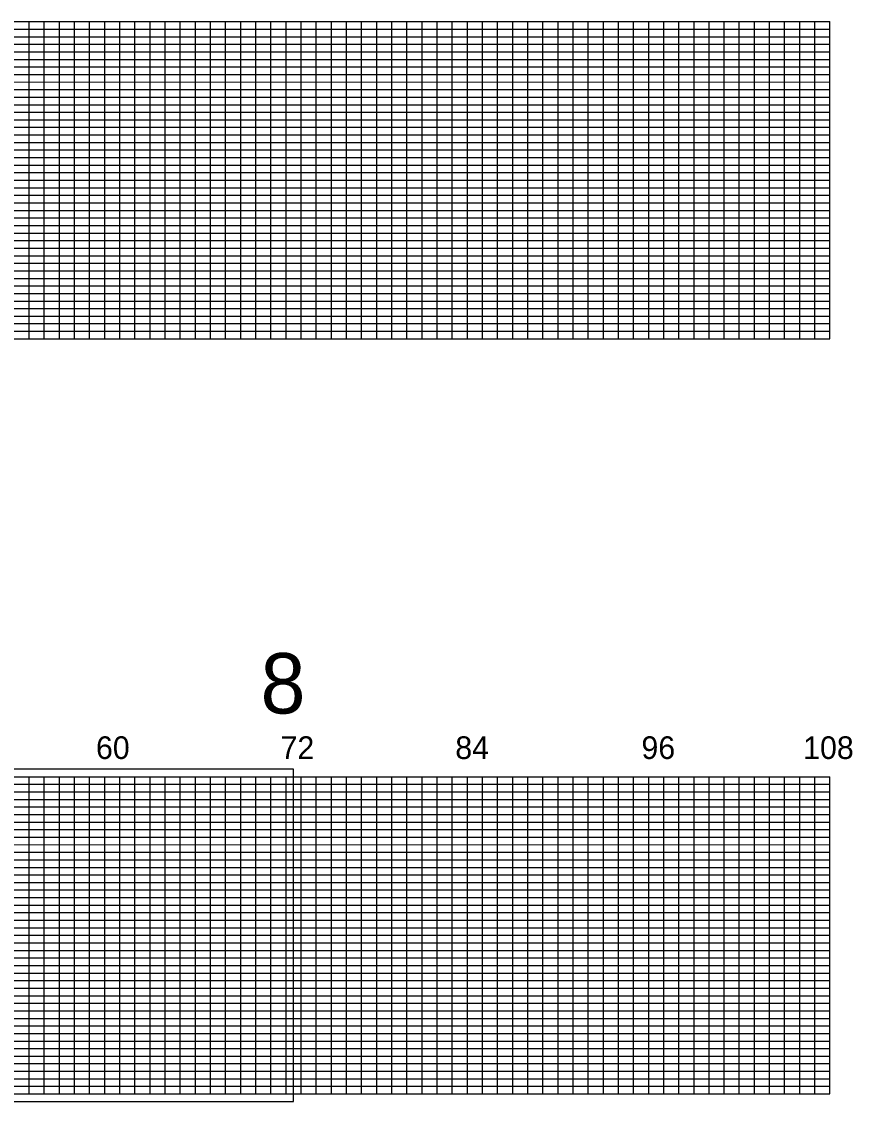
# Model space of a CAD drawing. Extents: x 1950433 to 1956806, y 750939 to 777666.
# Drawn here: x 1954051 to 1956801, y 758439 to 762014 of the extents above; entities that cross this region are included whole.
import ezdxf

# ---------------------------------------------------------------- set-up
doc = ezdxf.new("R2010")
doc.units = 0
for name, color, linetype in [('RD_PD_WallFill', 7, 'Continuous'), ('RD_SHT_IplotShp', 7, 'Continuous'), ('RD_Sketch8', 7, 'Continuous')]:
    doc.layers.add(name, color=color, linetype=linetype)

msp = doc.modelspace()

# ---------------------------------------------------------------- linework, layer by layer
at = {"layer": 'RD_PD_WallFill'}
for p, q in [((1951376.4, 762014.1), (1956726.4, 762014.2)), ((1954076.4, 760964.2), (1954076.4, 762014.2)), ((1954126.4, 760964.2), (1954126.4, 762014.2)), ((1954176.4, 760964.2), (1954176.4, 762014.2)), ((1954226.4, 760964.2), (1954226.4, 762014.2)), ((1954276.4, 760964.2), (1954276.4, 762014.2)), ((1954326.4, 760964.2), (1954326.4, 762014.2)), ((1954376.4, 760964.2), (1954376.4, 762014.2)), ((1954426.4, 760964.2), (1954426.4, 762014.2)), ((1954476.4, 760964.1), (1954476.4, 762014.2)), ((1954526.4, 760964.2), (1954526.4, 762014.2)), ((1954576.4, 760964.2), (1954576.4, 762014.2)), ((1954626.4, 760964.2), (1954626.4, 762014.2)), ((1954676.4, 760964.2), (1954676.4, 762014.2)), ((1954726.4, 760964.2), (1954726.4, 762014.2)), ((1954776.4, 760964.1), (1954776.4, 762014.2)), ((1954826.4, 760964.1), (1954826.4, 762014.2)), ((1954876.4, 760964.2), (1954876.4, 762014.2)), ((1954926.4, 760964.2), (1954926.4, 762014.2)), ((1954976.4, 760964.2), (1954976.4, 762014.2)), ((1955026.4, 760964.2), (1955026.4, 762014.2)), ((1955076.4, 760964.2), (1955076.4, 762014.2)), ((1955126.4, 760964.2), (1955126.4, 762014.2)), ((1955176.4, 760964.2), (1955176.4, 762014.2)), ((1955226.4, 760964.2), (1955226.4, 762014.2)), ((1955276.4, 760964.2), (1955276.4, 762014.2)), ((1955326.4, 760964.2), (1955326.4, 762014.2)), ((1955376.4, 760964.2), (1955376.4, 762014.2)), ((1955426.4, 760964.2), (1955426.4, 762014.2)), ((1955476.4, 760964.2), (1955476.4, 762014.2)), ((1955526.4, 760964.2), (1955526.4, 762014.2)), ((1955576.4, 760964.2), (1955576.4, 762014.2)), ((1955626.4, 760964.2), (1955626.4, 762014.2)), ((1955676.4, 760964.2), (1955676.4, 762014.2)), ((1955726.4, 760964.2), (1955726.4, 762014.2)), ((1955776.4, 760964.2), (1955776.4, 762014.2)), ((1955826.4, 760964.2), (1955826.4, 762014.2)), ((1955876.4, 760964.2), (1955876.4, 762014.2)), ((1955926.4, 760964.2), (1955926.4, 762014.2)), ((1955976.4, 760964.2), (1955976.4, 762014.2)), ((1956026.4, 760964.2), (1956026.4, 762014.2)), ((1956076.4, 760964.2), (1956076.4, 762014.2)), ((1956126.4, 760964.2), (1956126.4, 762014.2)), ((1956176.4, 760964.2), (1956176.4, 762014.2)), ((1956226.4, 760964.2), (1956226.4, 762014.2)), ((1956276.4, 760964.2), (1956276.4, 762014.2)), ((1956326.4, 760964.2), (1956326.4, 762014.2)), ((1956376.4, 760964.2), (1956376.4, 762014.2)), ((1956426.4, 760964.2), (1956426.4, 762014.2)), ((1956476.4, 760964.2), (1956476.4, 762014.2)), ((1956526.4, 760964.2), (1956526.4, 762014.2)), ((1956576.4, 760964.2), (1956576.4, 762014.2)), ((1956626.4, 760964.2), (1956626.4, 762014.2)), ((1956676.4, 760964.2), (1956676.4, 762014.2)), ((1956726.4, 760964.2), (1956726.4, 762014.2)), ((1951826.4, 761989.1), (1956726.4, 761989.1)), ((1951826.4, 761964.1), (1956726.4, 761964.1)), ((1951826.4, 761939.1), (1956726.4, 761939.1)), ((1951826.4, 761914.2), (1956726.4, 761914.1)), ((1951826.4, 761889.1), (1956726.4, 761889.2)), ((1951376.4, 761864.1), (1956726.4, 761864.1)), ((1951376.4, 761839.1), (1956726.4, 761839.1)), ((1951376.4, 761814.1), (1956726.4, 761814.2)), ((1951376.4, 761789.2), (1956726.4, 761789.1)), ((1951376.4, 761764.2), (1956726.4, 761764.2)), ((1951376.4, 761739.1), (1956726.4, 761739.1)), ((1951376.4, 761714.1), (1956726.4, 761714.1)), ((1951376.4, 761689.2), (1956726.4, 761689.1)), ((1951376.4, 761664.1), (1956726.4, 761664.1)), ((1951376.4, 761639.2), (1956726.4, 761639.1)), ((1951376.4, 761614.1), (1956726.4, 761614.1)), ((1951376.4, 761589.1), (1956726.4, 761589.2)), ((1951376.4, 761564.1), (1956726.4, 761564.1)), ((1951376.4, 761539.1), (1956726.4, 761539.2)), ((1951376.4, 761514.1), (1956726.4, 761514.1)), ((1951376.4, 761489.1), (1956726.4, 761489.1)), ((1951376.4, 761464.2), (1956726.4, 761464.1)), ((1951376.4, 761439.1), (1956726.4, 761439.1)), ((1951376.4, 761414.1), (1956726.4, 761414.1)), ((1951376.4, 761389.1), (1956726.4, 761389.1)), ((1951376.4, 761364.1), (1956726.4, 761364.2)), ((1951376.4, 761339.1), (1956726.4, 761339.1)), ((1951376.4, 761314.1), (1956726.4, 761314.1)), ((1951376.4, 761289.1), (1956726.4, 761289.1)), ((1951376.4, 761264.1), (1956726.4, 761264.1)), ((1951376.4, 761239.1), (1956726.4, 761239.1)), ((1951376.4, 761214.1), (1956726.4, 761214.1)), ((1951376.4, 761189.1), (1956726.4, 761189.1)), ((1951376.4, 761164.1), (1956726.4, 761164.1)), ((1951376.4, 761139.1), (1956726.4, 761139.1)), ((1951376.4, 761114.1), (1956726.4, 761114.1)), ((1951376.4, 761089.1), (1956726.4, 761089.1)), ((1951376.4, 761064.1), (1956726.4, 761064.1)), ((1951376.4, 761039.1), (1956726.4, 761039.1)), ((1951376.4, 761014.1), (1956726.4, 761014.1)), ((1951426.4, 760989.1), (1956726.4, 760989.1)), ((1951376.4, 760964.1), (1956726.4, 760964.1)), ((1951376.4, 759514.1), (1956726.4, 759514.2)), ((1954076.4, 758464.2), (1954076.4, 759514.2)), ((1954126.4, 758464.2), (1954126.4, 759514.2)), ((1954176.4, 758464.2), (1954176.4, 759514.2)), ((1954226.4, 758464.2), (1954226.4, 759514.2)), ((1954276.4, 758464.2), (1954276.4, 759514.2)), ((1954326.4, 758464.2), (1954326.4, 759514.2)), ((1954376.4, 758464.2), (1954376.4, 759514.2)), ((1954426.4, 758464.2), (1954426.4, 759514.2)), ((1954476.4, 758464.1), (1954476.4, 759514.2)), ((1954526.4, 758464.2), (1954526.4, 759514.2)), ((1954576.4, 758464.2), (1954576.4, 759514.2)), ((1954626.4, 758464.2), (1954626.4, 759514.2)), ((1954676.4, 758464.2), (1954676.4, 759514.2)), ((1954726.4, 758464.2), (1954726.4, 759514.2)), ((1954776.4, 758464.1), (1954776.4, 759514.2)), ((1954826.4, 758464.1), (1954826.4, 759514.2)), ((1954876.4, 758464.2), (1954876.4, 759514.2)), ((1954926.4, 758464.2), (1954926.4, 759514.2)), ((1954976.4, 758464.2), (1954976.4, 759514.2)), ((1955026.4, 758464.2), (1955026.4, 759514.2)), ((1955076.4, 758464.2), (1955076.4, 759514.2)), ((1955126.4, 758464.2), (1955126.4, 759514.2)), ((1955176.4, 758464.2), (1955176.4, 759514.2)), ((1955226.4, 758464.2), (1955226.4, 759514.2)), ((1955276.4, 758464.2), (1955276.4, 759514.2)), ((1955326.4, 758464.2), (1955326.4, 759514.2)), ((1955376.4, 758464.2), (1955376.4, 759514.2)), ((1955426.4, 758464.2), (1955426.4, 759514.2)), ((1955476.4, 758464.2), (1955476.4, 759514.2)), ((1955526.4, 758464.2), (1955526.4, 759514.2)), ((1955576.4, 758464.2), (1955576.4, 759514.2)), ((1955626.4, 758464.2), (1955626.4, 759514.2)), ((1955676.4, 758464.2), (1955676.4, 759514.2)), ((1955726.4, 758464.2), (1955726.4, 759514.2)), ((1955776.4, 758464.2), (1955776.4, 759514.2)), ((1955826.4, 758464.2), (1955826.4, 759514.2)), ((1955876.4, 758464.2), (1955876.4, 759514.2)), ((1955926.4, 758464.2), (1955926.4, 759514.2)), ((1955976.4, 758464.2), (1955976.4, 759514.2)), ((1956026.4, 758464.2), (1956026.4, 759514.2)), ((1956076.4, 758464.2), (1956076.4, 759514.2)), ((1956126.4, 758464.2), (1956126.4, 759514.2)), ((1956176.4, 758464.2), (1956176.4, 759514.2)), ((1956226.4, 758464.2), (1956226.4, 759514.2)), ((1956276.4, 758464.2), (1956276.4, 759514.2)), ((1956326.4, 758464.2), (1956326.4, 759514.2)), ((1956376.4, 758464.2), (1956376.4, 759514.2)), ((1956426.4, 758464.2), (1956426.4, 759514.2)), ((1956476.4, 758464.2), (1956476.4, 759514.2)), ((1956526.4, 758464.2), (1956526.4, 759514.2)), ((1956576.4, 758464.2), (1956576.4, 759514.2)), ((1956626.4, 758464.2), (1956626.4, 759514.2)), ((1956676.4, 758464.2), (1956676.4, 759514.2)), ((1956726.4, 758464.2), (1956726.4, 759514.2)), ((1951826.4, 759489.1), (1956726.4, 759489.1)), ((1951826.4, 759464.1), (1956726.4, 759464.1)), ((1951826.4, 759439.1), (1956726.4, 759439.1)), ((1951826.4, 759414.2), (1956726.4, 759414.1)), ((1951826.4, 759389.1), (1956726.4, 759389.2)), ((1951376.4, 759364.1), (1956726.4, 759364.1)), ((1951376.4, 759339.1), (1956726.4, 759339.1)), ((1951376.4, 759314.1), (1956726.4, 759314.2)), ((1951376.4, 759289.2), (1956726.4, 759289.1)), ((1951376.4, 759264.2), (1956726.4, 759264.2)), ((1951376.4, 759239.1), (1956726.4, 759239.1)), ((1951376.4, 759214.1), (1956726.4, 759214.1)), ((1951376.4, 759189.2), (1956726.4, 759189.1)), ((1951376.4, 759164.1), (1956726.4, 759164.1)), ((1951376.4, 759139.2), (1956726.4, 759139.1)), ((1951376.4, 759114.1), (1956726.4, 759114.1)), ((1951376.4, 759089.1), (1956726.4, 759089.2)), ((1951376.4, 759064.1), (1956726.4, 759064.1)), ((1951376.4, 759039.1), (1956726.4, 759039.2)), ((1951376.4, 759014.1), (1956726.4, 759014.1)), ((1951376.4, 758989.1), (1956726.4, 758989.1)), ((1951376.4, 758964.2), (1956726.4, 758964.1)), ((1951376.4, 758939.1), (1956726.4, 758939.1)), ((1951376.4, 758914.1), (1956726.4, 758914.1)), ((1951376.4, 758889.1), (1956726.4, 758889.1)), ((1951376.4, 758864.1), (1956726.4, 758864.2)), ((1951376.4, 758839.1), (1956726.4, 758839.1)), ((1951376.4, 758814.1), (1956726.4, 758814.1)), ((1951376.4, 758789.1), (1956726.4, 758789.1)), ((1951376.4, 758764.1), (1956726.4, 758764.1)), ((1951376.4, 758739.1), (1956726.4, 758739.1)), ((1951376.4, 758714.1), (1956726.4, 758714.1)), ((1951376.4, 758689.1), (1956726.4, 758689.1)), ((1951376.4, 758664.1), (1956726.4, 758664.1)), ((1951376.4, 758639.1), (1956726.4, 758639.1)), ((1951376.4, 758614.1), (1956726.4, 758614.1)), ((1951376.4, 758589.1), (1956726.4, 758589.1)), ((1951376.4, 758564.1), (1956726.4, 758564.1)), ((1951376.4, 758539.1), (1956726.4, 758539.1)), ((1951376.4, 758514.1), (1956726.4, 758514.1)), ((1951426.4, 758489.1), (1956726.4, 758489.1)), ((1951376.4, 758464.1), (1956726.4, 758464.1))]:
    msp.add_line(p, q, dxfattribs=at)
at = {"layer": 'RD_SHT_IplotShp'}
msp.add_lwpolyline([(1951351.4, 758439.1), (1954951.4, 758439.1), (1954951.4, 759539.1), (1951351.4, 759539.1)], close=True, dxfattribs=at)

# ---------------------------------------------------------------- texts
at = {"layer": 'RD_PD_WallFill'}
for s, p in [('60', (1954297.5, 759572.8)), ('72', (1954908.2, 759572.8)), ('84', (1955486.5, 759572.8)), ('96', (1956102.5, 759572.8)), ('108', (1956637.6, 759572.8))]:
    msp.add_text(s, height=75, dxfattribs=at).set_placement(p)
at = {"layer": 'RD_Sketch8'}
msp.add_text('8', height=200, dxfattribs=at).set_placement((1954842, 759723.4))

doc.saveas('drawing.dxf')
